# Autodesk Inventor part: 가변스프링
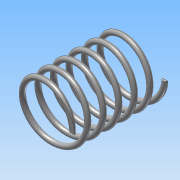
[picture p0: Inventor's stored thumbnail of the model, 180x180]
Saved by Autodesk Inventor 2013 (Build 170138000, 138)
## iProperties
Created: 2018-06
Part Number: 가변스프링
Material: 강철, 연강
Document SubType Name: Modeling
Designer: Administrator
Density: 1 g/cm^3
Mass: -0.137845 g
Surface Area: 106.475 cm^2
Volume: -0.137845 cm^3
Author: Administrator
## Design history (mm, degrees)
sketch "스케치1"
  geometry: L1 (0, 0)-(0, 73.25); L2 (0, 0)-(22.5, 0); L3 (0, 73.25)-(22.5, 73.25); C1 r 2 at (22.5, 0)
  constraints: 6 end point, 1 centre point, 1 coincident, 1 parallel, 1 perpendicular, 1 vertical
  dimensions: "d0" = 73.25 distance of L1.start L1.end (derived); "d1" = 22.5 distance of L1.start L2.end; "d2" = 22.5 distance of L1.end L3.end; "d3" = 4 diameter of C1
feature "코일1" sketch "스케치1" pitch "d4" = 10; turns "d6" = 6; dims "d5" = 73.25 (= d0), "d7" = 0, angle "d8" = 90 deg, angle "d9" = 90 deg, "d10" = 0, "d11" = 0
sketch "스케치2"
  geometry: L1 (73.25, 27.5)-(0, 27.5); L2 (0, 27.5)-(0, -27.5); L3 (0, -27.5)-(73.25, -27.5); L4 (73.25, -27.5)-(73.25, 27.5); 2 further points
  constraints: 8 end point, 2 parallel, 1 coincident, 1 horizontal, 1 midpoint, 1 perpendicular
  dimensions: "d12" = 73.25 distance of L1.start L1.end (derived); "d14" = 55 distance of L3.end L1.start
extrude "돌출1" sketch "스케치2" stored distance "d15" = 10; taper "d16" = 0 deg
node "솔리드1"
